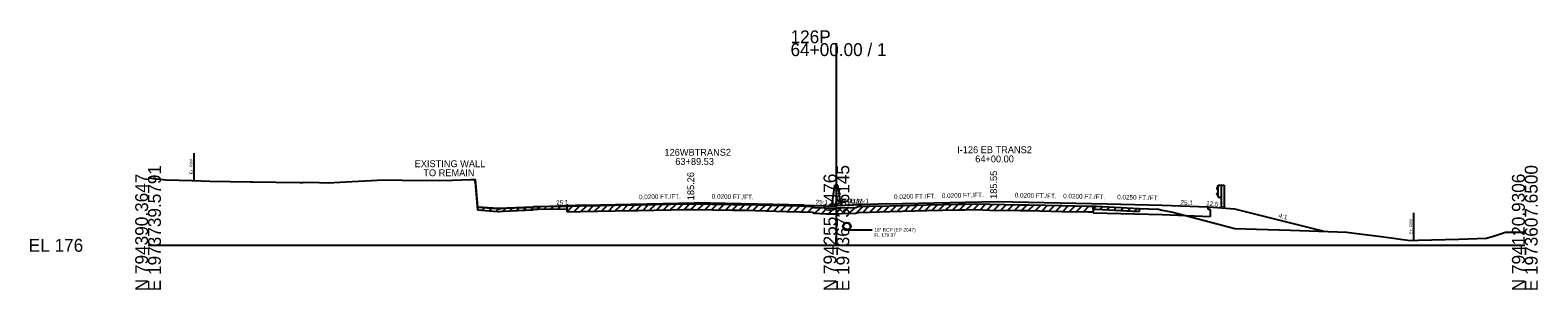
# Model space of a CAD drawing. Extents: x -161 to 1970889, y -4362 to 797231.
# Drawn here: x 2974.3 to 3302.8, y 490.3 to 546.9 of the extents above; entities that cross this region are included whole.
import ezdxf

# ---------------------------------------------------------------- set-up
doc = ezdxf.new("R2010")
doc.units = 0
for name, color, linetype in [('Default', 7, 'Continuous'), ('RD_GPK_XS_Cell', 7, 'Continuous'), ('RD_XS_Base', 7, 'Continuous'), ('RD_XS_EarthShd', 7, 'Continuous'), ('RD_XS_ExGround', 7, 'Continuous'), ('RD_XS_ExPaveRet', 7, 'Continuous'), ('RD_XS_ExRW', 7, 'Continuous'), ('RD_XS_GR', 7, 'Continuous'), ('RD_XS_MedBWall', 7, 'Continuous'), ('RD_XS_Misc_Line', 7, 'Continuous'), ('RD_XS_Pave', 7, 'Continuous'), ('RD_XS_PaveOvlay', 7, 'Continuous'), ('RD_XS_PaveShd', 7, 'Continuous'), ('RD_XS_Pipe', 7, 'Continuous'), ('RD_XS_TieSlope', 7, 'Continuous'), ('RD_XS_TX_Elev_EX', 7, 'Continuous'), ('RD_XS_TX_Elev_PR', 7, 'Continuous'), ('RD_XS_TX_MkPT', 7, 'Continuous'), ('RD_XS_TX_Notes', 7, 'Continuous'), ('RD_XS_TX_Profile', 7, 'Continuous'), ('RD_XS_TX_ShdSlope', 7, 'Continuous'), ('RD_XS_TX_Slope', 7, 'Continuous'), ('RD_XS_TX_Station', 7, 'Continuous')]:
    doc.layers.add(name, color=color, linetype=linetype)

msp = doc.modelspace()

# ---------------------------------------------------------------- linework, layer by layer
at = {"layer": 'RD_GPK_XS_Cell'}
for p, q in [((3150, 500), (3150, 544.02)), ((3000, 500), (3150, 500)), ((3150, 500), (3300, 500))]:
    msp.add_line(p, q, dxfattribs=at)
at = {"layer": 'RD_XS_Base'}
for p, q in [((3205.97, 507.09), (3209, 507.03)), ((3209, 507.03), (3221, 506.73)), ((3221, 506.73), (3231.5, 506.31)), ((3231, 507.81), (3231, 508.37)), ((3231.5, 507.79), (3231, 507.81)), ((3231.5, 506.31), (3231.5, 507.79))]:
    msp.add_line(p, q, dxfattribs=at)
at = {"layer": 'RD_XS_EarthShd'}
msp.add_line((3231, 508.37), (3233, 508.21), dxfattribs=at)
at = {"layer": 'RD_XS_ExGround'}
msp.add_lwpolyline([(3000, 514.67), (3000.34, 514.67), (3001.22, 514.58), (3003.86, 514.26), (3009.6, 514.12), (3013.44, 514), (3022.34, 513.85), (3022.68, 513.84), (3033.1, 513.66), (3033.69, 513.68), (3035.43, 513.74), (3039.25, 513.63), (3041.77, 513.75), (3051.27, 514.23), (3055.4, 514.18), (3063.56, 514.09), (3066.32, 514.19), (3070.28, 514.33), (3070.78, 514.33), (3071.3, 514.33), (3071.8, 508.34), (3076.11, 508), (3076.48, 507.98), (3077.41, 508.1), (3082.14, 508.27), (3083.74, 508.33), (3084.08, 508.47), (3084.93, 508.48), (3094.25, 508.59), (3105.53, 508.83), (3105.98, 508.84), (3106.69, 508.85), (3113.89, 508.98), (3117.26, 509.03), (3118.14, 509.05), (3118.86, 509.04), (3122.97, 508.98), (3127.39, 508.92), (3130.12, 508.88), (3139.13, 508.64), (3142.08, 508.57), (3144.77, 508.44), (3145.18, 508.24), (3147.75, 508.14), (3148.21, 508.12), (3150, 508.14), (3151.04, 508.16), (3154.25, 508.27), (3154.71, 508.42), (3157.17, 508.5), (3161.65, 508.63), (3169.69, 508.83), (3176.55, 508.95), (3178.02, 508.97), (3180.4, 509.02), (3183.42, 508.93), (3190.01, 508.83), (3191.95, 508.8), (3199.15, 508.65), (3204.93, 508.54), (3206.59, 508.53), (3213.26, 508.16), (3215.98, 508.02), (3220.16, 507.85), (3220.99, 507.67), (3223.32, 507.19), (3226.05, 506.49), (3236.79, 503.67), (3241.53, 503.51), (3248.92, 503.32), (3261.19, 502.87), (3262.78, 502.65), (3269.28, 501.84), (3275.02, 501.03), (3276.78, 501.1), (3285.63, 501.36), (3287.56, 501.44), (3291.68, 501.53), (3293.41, 502.07), (3295.82, 502.85), (3300, 502.85)], dxfattribs=at)
at = {"layer": 'RD_XS_ExPaveRet'}
for p, q in [((3071.3, 513.7), (3071.3, 514.33)), ((3071.3, 513.7), (3071.8, 507.71)), ((3071.8, 507.71), (3076.11, 507.38)), ((3076.11, 507.38), (3076.48, 507.35)), ((3076.48, 507.35), (3077.41, 507.47)), ((3077.41, 507.47), (3082.14, 507.65)), ((3082.14, 507.65), (3083.74, 507.71)), ((3083.74, 507.71), (3084.08, 507.85)), ((3084.08, 507.85), (3084.93, 507.86)), ((3084.93, 507.86), (3091.3, 507.93)), ((3091.3, 507.31), (3091.3, 508.56)), ((3091.3, 508.56), (3091.3, 507.93)), ((3091.3, 507.31), (3094.25, 507.34)), ((3094.25, 507.34), (3105.53, 507.58)), ((3105.53, 507.58), (3105.98, 507.59)), ((3105.98, 507.59), (3106.69, 507.6)), ((3106.69, 507.6), (3113.89, 507.73)), ((3113.89, 507.73), (3117.26, 507.78)), ((3117.26, 507.78), (3118.14, 507.8)), ((3118.14, 507.8), (3118.86, 507.79)), ((3118.86, 507.79), (3122.97, 507.73)), ((3122.97, 507.73), (3127.39, 507.67)), ((3127.39, 507.67), (3130.12, 507.63)), ((3130.12, 507.63), (3139.13, 507.39)), ((3139.13, 507.39), (3142.08, 507.32)), ((3142.08, 507.32), (3144.77, 507.19)), ((3144.77, 507.19), (3145.18, 506.99)), ((3145.18, 506.99), (3147.75, 506.89)), ((3147.75, 506.89), (3148.21, 506.87)), ((3148.21, 506.87), (3150, 506.89)), ((3150, 506.89), (3151.04, 506.91)), ((3151.04, 506.91), (3154.25, 507.02)), ((3154.25, 507.02), (3154.71, 507.17)), ((3154.71, 507.17), (3157.17, 507.25)), ((3157.17, 507.25), (3161.65, 507.38)), ((3161.65, 507.38), (3169.69, 507.58)), ((3169.69, 507.58), (3176.55, 507.7)), ((3176.55, 507.7), (3178.02, 507.72)), ((3178.02, 507.72), (3180.4, 507.77)), ((3180.4, 507.77), (3183.42, 507.68)), ((3183.42, 507.68), (3190.01, 507.58)), ((3190.01, 507.58), (3191.95, 507.55)), ((3191.95, 507.55), (3199.15, 507.4)), ((3199.15, 507.4), (3204.93, 507.29)), ((3204.93, 507.29), (3205.97, 507.28)), ((3205.97, 508.53), (3205.97, 507.28)), ((3205.97, 507.91), (3205.97, 508.53)), ((3205.97, 507.91), (3206.59, 507.9)), ((3206.59, 507.9), (3213.26, 507.53)), ((3213.26, 507.53), (3215.98, 507.39)), ((3215.98, 508.02), (3215.98, 507.39))]:
    msp.add_line(p, q, dxfattribs=at)
at = {"layer": 'RD_XS_ExRW'}
for p, q in [((3010, 520.1), (3010, 514.1)), ((3275.76, 507.06), (3275.76, 501.06))]:
    msp.add_line(p, q, dxfattribs=at)
at = {"layer": 'RD_XS_GR'}
for p, q in [((3233.15, 512.92), (3232.88, 512.48)), ((3233.15, 513.08), (3233.81, 513.08)), ((3233.15, 510.52), (3233.15, 513.08)), ((3233.81, 513.08), (3234.48, 513.08)), ((3233.81, 513.08), (3233.81, 508.14)), ((3234.48, 513.08), (3234.48, 508.03)), ((3232.88, 512.48), (3232.88, 512.37)), ((3232.88, 512.37), (3233.15, 511.93)), ((3232.88, 511.23), (3233.15, 511.67)), ((3232.88, 511.12), (3232.88, 511.23)), ((3233.15, 510.68), (3232.88, 511.12)), ((3233.15, 510.52), (3233.81, 510.52))]:
    msp.add_line(p, q, dxfattribs=at)
at = {"layer": 'RD_XS_MedBWall'}
for p, q in [((3149, 508.52), (3149.67, 513)), ((3150.33, 513.13), (3149.67, 513.13)), ((3149.67, 513), (3149.67, 513.13)), ((3151, 508.65), (3150.33, 513.13))]:
    msp.add_line(p, q, dxfattribs=at)
at = {"layer": 'RD_XS_Misc_Line'}
for p, q in [((3071.3, 513.7), (3071.35, 513.75)), ((3072.8, 507.64), (3073.38, 508.22)), ((3074.3, 507.52), (3074.88, 508.1)), ((3075.8, 507.4), (3076.38, 507.98)), ((3077.3, 507.46), (3077.96, 508.12)), ((3078.8, 507.52), (3079.45, 508.17)), ((3080.3, 507.58), (3080.95, 508.23)), ((3081.8, 507.63), (3082.45, 508.28)), ((3083.3, 507.69), (3084.08, 508.47)), ((3084.8, 507.85), (3085.43, 508.49)), ((3086.3, 507.87), (3086.93, 508.5)), ((3087.8, 507.89), (3088.43, 508.52)), ((3089.3, 507.91), (3089.93, 508.54)), ((3091.3, 507.31), (3092.56, 508.57)), ((3092.8, 507.33), (3094.06, 508.59)), ((3094.3, 507.35), (3095.58, 508.62)), ((3095.8, 507.38), (3097.08, 508.65)), ((3097.3, 507.41), (3098.58, 508.69)), ((3098.8, 507.44), (3100.08, 508.72)), ((3100.3, 507.47), (3101.58, 508.75)), ((3101.8, 507.5), (3103.08, 508.78)), ((3103.3, 507.54), (3104.58, 508.81)), ((3104.8, 507.57), (3106.08, 508.84)), ((3106.3, 507.6), (3107.57, 508.87)), ((3107.8, 507.62), (3109.07, 508.9)), ((3109.3, 507.65), (3110.57, 508.92)), ((3110.8, 507.68), (3112.07, 508.95)), ((3112.3, 507.7), (3113.57, 508.98)), ((3113.8, 507.73), (3115.07, 509)), ((3115.3, 507.75), (3116.57, 509.02)), ((3116.8, 507.77), (3118.07, 509.05)), ((3118.3, 507.8), (3119.53, 509.03)), ((3119.8, 507.77), (3121.03, 509)), ((3121.3, 507.75), (3122.53, 508.98)), ((3122.8, 507.73), (3124.03, 508.96)), ((3124.3, 507.71), (3125.53, 508.94)), ((3125.8, 507.69), (3127.03, 508.92)), ((3127.3, 507.67), (3128.53, 508.9)), ((3128.8, 507.65), (3130.03, 508.88)), ((3130.3, 507.62), (3131.52, 508.84)), ((3131.8, 507.58), (3133.02, 508.8)), ((3133.3, 507.55), (3134.52, 508.76)), ((3134.8, 507.51), (3136.02, 508.73)), ((3136.3, 507.47), (3137.52, 508.69)), ((3137.8, 507.43), (3139.02, 508.65)), ((3139.3, 507.39), (3140.52, 508.61)), ((3140.8, 507.35), (3142.02, 508.57)), ((3142.3, 507.31), (3143.49, 508.5)), ((3143.8, 507.24), (3144.93, 508.36)), ((3145.3, 506.99), (3146.5, 508.19)), ((3146.8, 506.93), (3148, 508.13)), ((3148.3, 506.87), (3149.56, 508.14)), ((3149.8, 506.89), (3151.06, 508.16)), ((3151.3, 506.92), (3152.59, 508.21)), ((3152.8, 506.97), (3154.09, 508.26)), ((3154.3, 507.03), (3155.72, 508.45)), ((3155.8, 507.21), (3157.09, 508.5)), ((3157.3, 507.25), (3158.59, 508.54)), ((3158.8, 507.3), (3160.09, 508.58)), ((3160.3, 507.34), (3161.59, 508.63)), ((3161.8, 507.38), (3163.08, 508.66)), ((3163.3, 507.42), (3164.58, 508.7)), ((3164.8, 507.46), (3166.08, 508.74)), ((3166.3, 507.5), (3167.58, 508.78)), ((3167.8, 507.54), (3169.08, 508.82)), ((3169.3, 507.57), (3170.57, 508.85)), ((3170.8, 507.6), (3172.07, 508.87)), ((3172.3, 507.63), (3173.57, 508.9)), ((3173.8, 507.65), (3175.07, 508.92)), ((3175.3, 507.68), (3176.57, 508.95)), ((3176.8, 507.7), (3178.07, 508.97)), ((3178.3, 507.73), (3179.57, 509)), ((3179.8, 507.75), (3181.04, 509)), ((3181.3, 507.74), (3182.51, 508.95)), ((3182.8, 507.69), (3184.02, 508.92)), ((3184.3, 507.66), (3185.53, 508.9)), ((3185.8, 507.64), (3187.03, 508.87)), ((3187.3, 507.62), (3188.53, 508.85)), ((3188.8, 507.6), (3190.03, 508.83)), ((3190.3, 507.57), (3191.53, 508.81)), ((3191.8, 507.55), (3193.02, 508.78)), ((3193.3, 507.52), (3194.52, 508.75)), ((3194.8, 507.49), (3196.02, 508.72)), ((3196.3, 507.46), (3197.52, 508.69)), ((3197.8, 507.43), (3199.02, 508.66)), ((3199.3, 507.4), (3200.52, 508.63)), ((3200.8, 507.37), (3202.02, 508.6)), ((3202.3, 507.34), (3203.52, 508.57)), ((3203.8, 507.31), (3205.03, 508.54)), ((3205.97, 507.91), (3206.59, 508.53)), ((3207.47, 507.85), (3208.06, 508.45)), ((3208.97, 507.77), (3209.56, 508.36)), ((3210.47, 507.69), (3211.06, 508.28)), ((3211.97, 507.61), (3212.56, 508.2)), ((3213.47, 507.52), (3214.07, 508.12)), ((3214.97, 507.44), (3215.57, 508.04))]:
    msp.add_line(p, q, dxfattribs=at)
at = {"layer": 'RD_XS_Pave'}
for p, q in [((3095, 508.78), (3119, 509.26)), ((3143, 508.78), (3119, 509.26)), ((3161, 509.07), (3185, 509.55)), ((3185, 509.55), (3209, 509.07)), ((3209, 509.07), (3221, 508.77))]:
    msp.add_line(p, q, dxfattribs=at)
at = {"layer": 'RD_XS_PaveOvlay'}
for p, q in [((3091.3, 508.56), (3094.25, 508.59)), ((3094.25, 508.59), (3105.53, 508.83)), ((3105.53, 508.83), (3105.98, 508.84)), ((3105.98, 508.84), (3106.69, 508.85)), ((3106.69, 508.85), (3113.89, 508.98)), ((3113.89, 508.98), (3117.26, 509.03)), ((3117.26, 509.03), (3118.14, 509.05)), ((3118.14, 509.05), (3118.86, 509.04)), ((3118.86, 509.04), (3122.97, 508.98)), ((3122.97, 508.98), (3127.39, 508.92)), ((3127.39, 508.92), (3130.12, 508.88)), ((3130.12, 508.88), (3139.13, 508.64)), ((3139.13, 508.64), (3142.08, 508.57)), ((3142.08, 508.57), (3144.77, 508.44)), ((3144.77, 508.44), (3145.18, 508.24)), ((3145.18, 508.24), (3147.75, 508.14)), ((3147.75, 508.14), (3148.21, 508.12)), ((3148.21, 508.12), (3150, 508.14)), ((3150, 508.14), (3151.04, 508.16)), ((3151.04, 508.16), (3154.25, 508.27)), ((3154.25, 508.27), (3154.71, 508.42)), ((3154.71, 508.42), (3157.17, 508.5)), ((3157.17, 508.5), (3161.65, 508.63)), ((3161.65, 508.63), (3169.69, 508.83)), ((3169.69, 508.83), (3176.55, 508.95)), ((3176.55, 508.95), (3178.02, 508.97)), ((3178.02, 508.97), (3180.4, 509.02)), ((3180.4, 509.02), (3183.42, 508.93)), ((3183.42, 508.93), (3190.01, 508.83)), ((3190.01, 508.83), (3191.95, 508.8)), ((3191.95, 508.8), (3199.15, 508.65)), ((3199.15, 508.65), (3204.93, 508.54)), ((3204.93, 508.54), (3205.97, 508.53)), ((3205.97, 508.53), (3205.97, 507.09))]:
    msp.add_line(p, q, dxfattribs=at)
msp.add_lwpolyline([(3071.84, 508.34), (3076.11, 508), (3076.48, 507.98), (3077.41, 508.1), (3082.14, 508.27), (3083.74, 508.33), (3084.08, 508.47), (3084.93, 508.48), (3091.3, 508.56)], dxfattribs=at)
at = {"layer": 'RD_XS_PaveShd'}
for p, q in [((3076.35, 508.04), (3071.84, 508.34)), ((3095, 508.78), (3076.35, 508.04)), ((3143, 508.78), (3150, 508.5)), ((3161, 509.07), (3150, 508.63)), ((3150, 508.49), (3150, 508.63)), ((3221, 508.77), (3231, 508.37))]:
    msp.add_line(p, q, dxfattribs=at)
at = {"layer": 'RD_XS_Pipe'}
msp.add_line((3152.77, 503.37), (3157.77, 503.37), dxfattribs=at)
for radius in [0.85, 0.75]:
    msp.add_circle((3152.27, 504.12), radius, dxfattribs=at)
at = {"layer": 'RD_XS_TieSlope'}
for p, q in [((3233, 508.21), (3236.75, 507.92)), ((3236.75, 507.92), (3256.21, 503.05))]:
    msp.add_line(p, q, dxfattribs=at)

# ---------------------------------------------------------------- texts
at = {"layer": 'Default'}
msp.add_text('35', height=1.5, dxfattribs=at).set_placement((3150, 508.5))
at = {"layer": 'RD_GPK_XS_Cell'}
for s, p in [('126P', (3140, 544.02)), ('64+00.00 / 1', (3140, 541.22)), ('EL 176', (2974, 498.6))]:
    msp.add_text(s, height=2.8, dxfattribs=at).set_placement(p)
for s, p in [('E 1973739.5791', (3002.8, 490)), ('E 1973673.6145', (3152.8, 490)), ('E 1973607.6500', (3302.8, 490)), ('N 794390.3647', (3000, 490)), ('N 794255.6476', (3150, 490)), ('N 794120.9306', (3300, 490))]:
    msp.add_text(s, height=2.8, rotation=90, dxfattribs=at).set_placement(p)
at = {"layer": 'RD_XS_ExRW'}
for p in [(3009.75, 515.49), (3275.51, 502.44)]:
    msp.add_text('Ex. R/W ', height=0.65, rotation=90, dxfattribs=at).set_placement(p)
at = {"layer": 'RD_XS_Pipe'}
for s, p in [('18" RCP (EP-2047)', (3158.27, 503)), ('FL 179.37', (3158.27, 501.87))]:
    msp.add_text(s, height=0.75, dxfattribs=at).set_placement(p)
at = {"layer": 'RD_XS_TX_Elev_EX'}
msp.add_text('184.14', height=1, rotation=90, dxfattribs=at).set_placement((3151, 508.14))
at = {"layer": 'RD_XS_TX_Elev_PR'}
for s, p in [(' 185.26', (3119, 509.26)), (' 185.55', (3185, 509.55))]:
    msp.add_text(s, height=1.5, rotation=90, dxfattribs=at).set_placement(p)
at = {"layer": 'RD_XS_TX_MkPT'}
for s, p in [('WBW', (3149, 508.52)), ('EBW', (3151, 508.65))]:
    msp.add_text(s, height=1.5, dxfattribs=at).set_placement(p)
at = {"layer": 'RD_XS_TX_Notes'}
for s, p in [('EXISTING WALL', (3058.1, 517.02)), ('TO REMAIN', (3059.99, 515.05))]:
    msp.add_text(s, height=1.5, dxfattribs=at).set_placement(p)
at = {"layer": 'RD_XS_TX_Profile'}
for rotation, p in [(2.2906, (3088.94, 508.79)), (357.7094, (3145.46, 508.93)), (2.2906, (3154.44, 509.06)), (357.7094, (3224.96, 508.86))]:
    msp.add_text('25:1', height=1, rotation=rotation, dxfattribs=at).set_placement(p)
at = {"layer": 'RD_XS_TX_ShdSlope'}
msp.add_text('12.5:1', height=1, rotation=355.4261, dxfattribs=at).set_placement((3230.54, 508.66))
at = {"layer": 'RD_XS_TX_Slope'}
for s, rotation, p in [('0.0200 FT./FT.', 1.1458, (3106.98, 510.02)), ('0.0200 FT./FT.', 358.8542, (3122.83, 510.18)), ('0.0200 FT./FT.', 1.1458, (3162.56, 510.07)), ('0.0200 FT./FT.', 1.1458, (3172.98, 510.31)), ('0.0200 FT./FT.', 358.569, (3188.84, 510.45)), ('0.0200 FT./FT.', 358.569, (3199.4, 510.26)), ('0.0250 FT./FT.', 358.5679, (3211.17, 510.03)), ('4:1', 345.9638, (3246.28, 506.05))]:
    msp.add_text(s, height=1, rotation=rotation, dxfattribs=at).set_placement(p)
at = {"layer": 'RD_XS_TX_Station'}
for s, p in [('126WBTRANS2', (3112.53, 519.51)), ('I-126 EB TRANS2', (3176.31, 520.07)), ('64+00.00', (3180.24, 518.07)), ('63+89.53', (3114.89, 517.51))]:
    msp.add_text(s, height=1.5, dxfattribs=at).set_placement(p)

doc.saveas('drawing.dxf')
